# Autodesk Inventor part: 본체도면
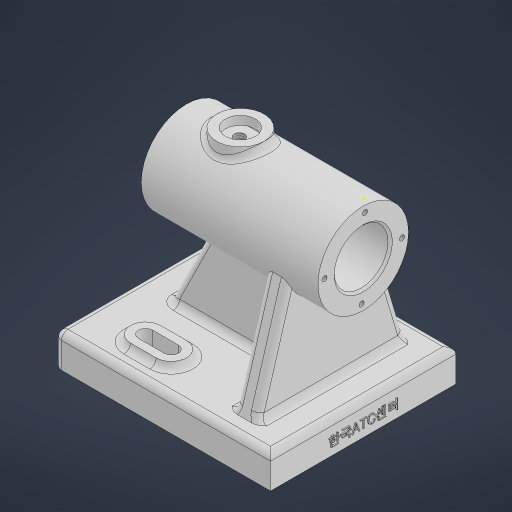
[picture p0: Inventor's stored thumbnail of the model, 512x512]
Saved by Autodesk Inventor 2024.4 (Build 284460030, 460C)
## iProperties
Created: 2026-09
Part Number: 본체도면
Material: 일반
Document SubType Name: Modeling
Designer: user
Density: 1 g/cm^3
Appearance: 기본값
Author: user
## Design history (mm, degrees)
sketch "스케치1"
  geometry: L1 (-82, 72)-(0, 72); L2 (-82, 93)-(0, 93); L3 (0, 93)-(0, 84.5); L4 (0, 84.5)-(-20, 84.5); L5 (-20, 84.5)-(-20, 86.5); L6 (-20, 86.5)-(-82, 86.5); L7 (-82, 86.5)-(-82, 93); 2 further points
  constraints: 14 end point, 5 perpendicular, 3 vertical alignment, 2 horizontal, 1 midpoint
  dimensions: "d0" = 82 distance of L1.start L1.end; "d1" = 72 distance from line of L1 point (0, 0); "d2" = 42 diameter of L2 L1; "d3" = 25 diameter of L4 L1; "d4" = 29 diameter of L6 L1; "d6" = 62 distance between parallel lines of L7 L5
revolve "회전1" sketch "스케치1" stored, may be unused: angle "d7" = 90 deg
sketch "스케치2"
  geometry: L1 (0, 0)-(0, 43); L2 (0, 43)-(100, 43); L3 (100, 43)-(100, -43); L4 (100, -43)-(0, -43); L5 (0, -43)-(0, 43); L6 (82, 21)-(82, -21) reference; 3 further points
  constraints: 10 end point, 3 perpendicular, 2 midpoint, 2 vertical, 1 horizontal alignment, 1 point on line
  dimensions: "d8" = 100 distance of L1.end L2.end; "d9" = 86 distance between parallel lines of L4 L2
extrude "돌출1" join sketch "스케치2" distance "d10" = 15; taper "d11" = 0 deg
sketch "스케치3"
  geometry: L1 (-100, 43)-(-100, -43) reference; L2 (0, 0)-(-100, 0); L3 (-62, 34)-(-74, 34); L4 (-74, 20)-(-62, 20); A1 r 7 centre (-74, 27) between (-74, 34) and (-74, 20); A2 r 7 centre (-62, 27) between (-62, 20) and (-62, 34)
  constraints: 6 end point, 4 point on circle, 4 tangent, 2 centre point, 1 horizontal, 1 midpoint, 1 parallel
  dimensions: "d15" = 14 distance between parallel lines of L4 L3; "d16" = 54 diameter of A1.centre L2; "d17" = 26 distance from line of A1.centre L1; "d18" = 12 distance of A2.centre A1.centre
extrude "돌출2" join sketch "스케치3" distance "d19" = 3; taper "d20" = 0 deg
sketch "스케치4"
  geometry: L1 (-74, 20)-(-62, 20) reference; L2 (-62, 34)-(-74, 34) reference; L3 (-74, 23.7)-(-62, 23.7); L4 (-62, 30.3)-(-74, 30.3); A1 r 7 centre (-74, 27) between (-74, 34) and (-74, 20) reference; A2 r 7 centre (-62, 27) between (-62, 20) and (-62, 34) reference; A3 r 3.3 centre (-74, 27) between (-74, 30.3) and (-74, 23.7); A4 r 3.3 centre (-62, 27) between (-62, 23.7) and (-62, 30.3); 1 further point
  constraints: 4 end point, 4 point on circle, 2 centre point, 3 other
  dimensions: "d21" = 6.6 distance between parallel lines of L3 L4
extrude "돌출3" cut sketch "스케치4" extent not by distance; stored distance "d22" = 0; taper "d23" = 0 deg
fillet "모깎기1" dims "d24" = 3
node "작업 평면1"
sketch "스케치8"
  geometry: 1 further point
sketch "스케치9"
  geometry: L1 (-82, -21)-(-82, 21) reference; L2 (0, -21)-(0, 21) reference; C1 r 11 at (-57, 0); C2 r 7 at (-57, 0); 2 further points
  constraints: 2 centre point, 1 coincident, 1 horizontal alignment, 1 midpoint
  dimensions: "d46" = 22 diameter of C1; "d47" = 14 diameter of C2; "d48" = 25 distance from line of C1.centre L1
extrude "돌출4" join sketch "스케치9" stored distance "d49" = 10; taper "d50" = 0 deg
sketch "스케치10"
  geometry: 2 further points
hole "구멍1" sketch "스케치10" at (-0.482, 0) diameter "d51" = 4.917; stored, may be unused: countersink angle "d55" = 90 deg, drill point angle "d57" = 118 deg; dims "d52" = 12, "d53" = 4, "d54" = 2, "d56" = 17.1
node "작업 평면2"
sketch "스케치11"
  geometry: L1 (86, 15)-(0, 15) reference; L2 (23.028, 65.511)-(8, 15); L3 (62.972, 65.511)-(78, 15); A1 r 21 centre (43, 72) between (23.028, 65.511) and (62.972, 65.511) reference; 1 further point
  constraints: 4 end point, 2 point on circle, 2 point on line, 1 equal length
  dimensions: "d59" = 8 distance of L1.end L2.end; "d60" = 8 distance of L3.end L1.start (= d59)
extrude "돌출5" join sketch "스케치11" distance "d61" = 10; taper "d62" = 0 deg
sketch "스케치13"
  geometry: L1 (-82, 51)-(0, 51) reference; L2 (0, 15)-(-100, 15) reference; L3 (-67.176, 51)-(-85, 15); L4 (-67.176, 51)-(-25, 51); L5 (-25, 65.511)-(-25, 15) reference; L6 (-25, 15)-(-85, 15); 1 further point
  constraints: 6 end point, 4 point on line, 1 collinear
  dimensions: "d65" = 15 distance of L2.end L3.end
extrude "돌출6" join sketch "스케치13" stored distance "d66" = 10; taper "d67" = 0 deg
fillet "모깎기2" dims "d68" = 3
fillet "모깎기3" dims "d69" = 3
fillet "모깎기4" dims "d70" = 3
sketch "스케치14" dims "d78" = 36
  geometry: C1 r 21 at (0, 0) reference; 3 further points
  constraints: 1 coincident, 3 other
hole "구멍2" sketch "스케치14" at (-0.788, 17.983) diameter "d71" = 2.459; stored, may be unused: countersink angle "d75" = 90 deg, drill point angle "d77" = 118 deg; dims "d72" = 8, "d73" = 4, "d74" = 2, "d76" = 10
chamfer "모따기1" distance "d85" = 1; stored, may be unused: second distance "d86" = 2, angle "d87" = 45 deg
chamfer "모따기2" distance "d88" = 1; stored, may be unused: second distance "d89" = 2, angle "d90" = 45 deg
node "작업 평면3"
sketch "스케치15"
  geometry: 1 further point
sketch "스케치16"
  geometry: L1 (0, 0)-(86, 0) reference; 3 further points
  constraints: 1 midpoint, 1 vertical alignment, 1 other
  dimensions: "d92" = 6 distance from line of point (43, 6) L1
feature "엠보싱1" sketch "스케치16" dims "d93" = 0.5, "d94" = 0
sketch "스케치18"
  geometry: C1 r 7 at (-57, 0) reference; C2 r 7 at (-57, 0); 1 further point
  constraints: 1 centre point, 1 coincident
extrude "돌출7" cut sketch "스케치18" distance "d96" = 4; taper "d97" = 0 deg
node "솔리드1"
mirror "미러1"
pattern_circular "원형 패턴2" dims angle "d83" = 360 deg
mirror "미러2"
node "투영된 루프2"
feature "A9D066F2-1C7D-4E18-AEED-F7BC21143FA4" dims "d51" = 4.917, "d52" = 12, "d53" = 4, "d54" = 2, "d55" = 90 deg, "d56" = 17.1, "d57" = 118 deg
other parameters: "d45" = -96, "d58" = -15, "d91" = -41
